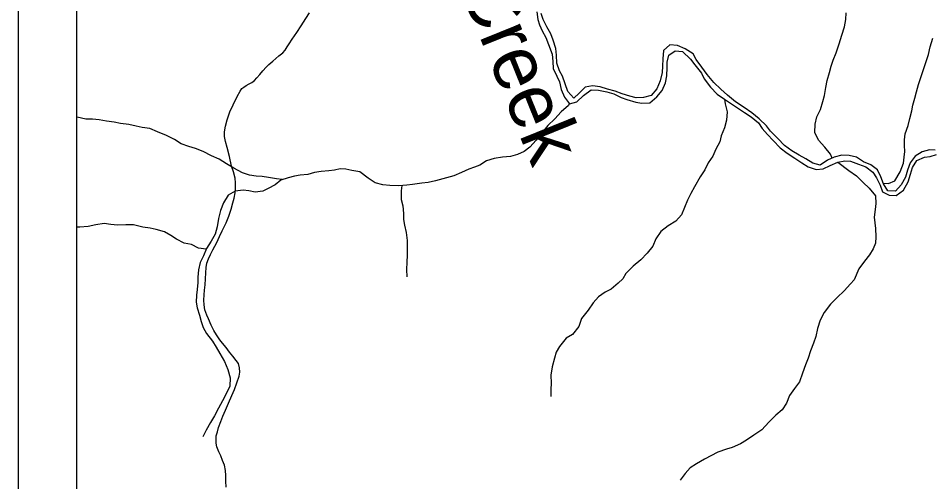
# Model space of a CAD drawing. Extents: x 0 to 44, y -23.8 to 22.
# Drawn here: x 2 to 3.565, y 16.572 to 17.366 of the extents above; entities that cross this region are included whole.
import ezdxf

# ---------------------------------------------------------------- set-up
doc = ezdxf.new("R2010")
doc.units = 0
for name, color, linetype in [('Default', 7, 'Continuous'), ('GM_X_Minor_River', 7, 'Continuous'), ('GM_X_Minor_River_Text', 7, 'Continuous'), ('GM_X_Township_Road', 7, 'Continuous'), ('SH_Cut_Line', 7, 'Continuous'), ('SH_Data', 7, 'Continuous')]:
    doc.layers.add(name, color=color, linetype=linetype)

msp = doc.modelspace()

# ---------------------------------------------------------------- linework, layer by layer
at = {"layer": 'Default'}
msp.add_lwpolyline([(2.3497, 20.9), (2.1, 20.9), (2.1, 14.1), (2.838, 14.1), (3.0317, 14.1856), (3.8639, 14.5533), (4.3443, 14.7655), (4.4538, 14.8144), (4.856, 14.9939), (4.5387, 15.7097), (4.3476, 16.1408), (4.1422, 16.6361), (4.026, 16.9163), (3.7907, 17.4383), (3.763, 17.5087), (3.455, 18.29), (3.1789, 18.9421), (3.1321, 19.0527), (3.0496, 19.2474), (3.0092, 19.3427), (2.8013, 19.8369), (2.472, 20.6113)], close=True, dxfattribs=at)
at = {"layer": 'GM_X_Minor_River'}
for points in [[(2.888, 17.377), (2.8901, 17.3638), (2.8931, 17.3543), (2.8975, 17.3444), (2.9039, 17.3326), (2.908, 17.3208), (2.9143, 17.3044), (2.9157, 17.2919), (2.9163, 17.2798), (2.9223, 17.2668), (2.9271, 17.2569), (2.9297, 17.244), (2.9356, 17.2307), (2.9442, 17.2189), (2.9568, 17.2226), (2.9682, 17.2335), (2.9815, 17.2432), (2.9936, 17.2428), (3.0084, 17.24), (3.0201, 17.2361), (3.0325, 17.2303), (3.0423, 17.2268), (3.0578, 17.2218), (3.068, 17.2202), (3.082, 17.2208), (3.0939, 17.231), (3.1027, 17.2423), (3.1088, 17.2551), (3.1112, 17.2672), (3.1117, 17.2813), (3.1117, 17.2907), (3.1141, 17.3025), (3.1251, 17.31), (3.138, 17.3091), (3.1515, 17.2957), (3.159, 17.2858), (3.1703, 17.2717), (3.1751, 17.2618), (3.1856, 17.2477), (3.1972, 17.2355), (3.2096, 17.227)], [(3.2692, 17.1936), (3.2564, 17.2035), (3.2432, 17.2131), (3.2285, 17.2227), (3.2146, 17.2342), (3.2037, 17.2441), (3.1917, 17.256), (3.1801, 17.2693), (3.1711, 17.2819), (3.161, 17.2949), (3.1561, 17.3048), (3.1422, 17.3132), (3.129, 17.319), (3.1161, 17.3203), (3.1051, 17.3105), (3.1038, 17.2965), (3.1037, 17.2836), (3.1029, 17.2726), (3.0998, 17.2586), (3.094, 17.2446), (3.084, 17.2333), (3.0711, 17.23), (3.0586, 17.2294), (3.0473, 17.2325), (3.0345, 17.2364), (3.0224, 17.2406), (3.0092, 17.2441), (2.9967, 17.2484), (2.9835, 17.25), (2.9713, 17.2479), (2.961, 17.2377), (2.9515, 17.2291), (2.9414, 17.2401), (2.9366, 17.2534), (2.9321, 17.2664), (2.9269, 17.2759), (2.9225, 17.2888), (2.9218, 17.3028), (2.9208, 17.3138), (2.9163, 17.3283), (2.9123, 17.3393), (2.9052, 17.3511), (2.8992, 17.3637), (2.8959, 17.374)], [(3.3941, 17.1264), (3.391, 17.1327), (3.3816, 17.1449), (3.3707, 17.1571), (3.3644, 17.1701), (3.3653, 17.1841), (3.3676, 17.197), (3.3742, 17.2094), (3.3781, 17.2234), (3.3808, 17.2336), (3.3835, 17.2469), (3.3855, 17.259), (3.3894, 17.2726), (3.3922, 17.2836), (3.396, 17.2942), (3.401, 17.3067), (3.4061, 17.3222), (3.4108, 17.3369), (3.415, 17.3513), (3.4178, 17.3638), (3.4182, 17.3748)], [(3.4815, 17.0831), (3.4909, 17.083), (3.5015, 17.0875), (3.5107, 17.1026), (3.5161, 17.1177), (3.5177, 17.1279), (3.5186, 17.1378), (3.5183, 17.148), (3.518, 17.1575), (3.5192, 17.1677), (3.5242, 17.1821), (3.5273, 17.1942), (3.5305, 17.2071), (3.5324, 17.2169), (3.5356, 17.229), (3.5387, 17.2396), (3.5422, 17.2521), (3.5453, 17.2627), (3.5507, 17.2778), (3.555, 17.2918), (3.5592, 17.3035), (3.562, 17.3171), (3.5663, 17.3319)], [(2.9437, 17.2196), (2.9423, 17.2162), (2.9301, 17.2057), (2.9191, 17.1937), (2.9072, 17.182), (2.8962, 17.1684), (2.887, 17.1571), (2.8763, 17.1451), (2.8668, 17.1376), (2.8554, 17.1324), (2.8429, 17.1291), (2.8296, 17.1276), (2.8152, 17.1255), (2.8023, 17.1214), (2.7909, 17.1143), (2.7814, 17.1106), (2.7719, 17.1072), (2.759, 17.1017), (2.7461, 17.0957), (2.7271, 17.0905), (2.7146, 17.0872), (2.7021, 17.0847), (2.6911, 17.0832), (2.6752, 17.0811), (2.6653, 17.08), (2.6517, 17.079), (2.6362, 17.0791), (2.6244, 17.0803), (2.6116, 17.0839), (2.5996, 17.0919), (2.5853, 17.1026), (2.5716, 17.105), (2.5611, 17.1074), (2.5512, 17.1078), (2.5414, 17.1053), (2.5319, 17.1042), (2.519, 17.1032), (2.5073, 17.1014), (2.4959, 17.0984), (2.483, 17.097), (2.4732, 17.0952), (2.4625, 17.0926), (2.4496, 17.0885), (2.4401, 17.0807), (2.4283, 17.0739), (2.4188, 17.0698), (2.4059, 17.068), (2.395, 17.07), (2.3852, 17.0712), (2.3715, 17.0698), (2.3597, 17.0627), (2.3517, 17.0495), (2.3463, 17.0363), (2.3431, 17.023), (2.3407, 17.0086), (2.3372, 16.9958), (2.3303, 16.9837), (2.3227, 16.9716), (2.3173, 16.9591), (2.3115, 16.9474), (2.3088, 16.9349), (2.3073, 16.9221)], [(3.2096, 17.227), (3.2107, 17.2194), (3.214, 17.2054), (3.2132, 17.1914), (3.2096, 17.1781), (3.2042, 17.1645), (3.2015, 17.1539), (3.1946, 17.1418), (3.19, 17.1297), (3.1815, 17.1181), (3.1758, 17.1063), (3.1681, 17.0943), (3.1585, 17.0773), (3.152, 17.0656), (3.1466, 17.0542), (3.1412, 17.0418), (3.1362, 17.0293), (3.1266, 17.0184), (3.1133, 17.0105), (3.1004, 17.0004), (3.0919, 16.9879), (3.0869, 16.9755), (3.0774, 16.9634), (3.0663, 16.9521), (3.053, 16.9409), (3.0408, 16.9288), (3.0354, 16.9194)], [(3.2096, 17.227), (3.2217, 17.219), (3.2319, 17.2121), (3.2439, 17.2044), (3.2552, 17.1967), (3.268, 17.1868), (3.2744, 17.1772), (3.2834, 17.1669), (3.2931, 17.1566), (3.3048, 17.144), (3.3172, 17.1344), (3.33, 17.126), (3.342, 17.1179), (3.3533, 17.1114), (3.3665, 17.1067), (3.379, 17.1078), (3.3908, 17.1138), (3.4037, 17.119), (3.4159, 17.1215), (3.4257, 17.1211), (3.4393, 17.116), (3.4517, 17.111), (3.4638, 17.1022), (3.4698, 17.0927), (3.4765, 17.0801), (3.4805, 17.0683), (3.4919, 17.0625), (3.504, 17.0621), (3.5165, 17.0714), (3.5246, 17.0858), (3.5281, 17.0986), (3.5316, 17.1104), (3.5389, 17.1224), (3.5522, 17.128), (3.562, 17.1291), (3.5727, 17.1324)], [(2.4519, 17.0893), (2.4425, 17.0905), (2.4289, 17.0929), (2.4175, 17.0945), (2.4077, 17.0953), (2.396, 17.0969), (2.3839, 17.1008), (2.3695, 17.1089), (2.3567, 17.1162), (2.3443, 17.1242), (2.3311, 17.1304), (2.3168, 17.1374), (2.3036, 17.1428), (2.2922, 17.1463), (2.279, 17.1509), (2.2674, 17.1582), (2.2538, 17.1651), (2.2387, 17.1713), (2.2255, 17.1771), (2.2123, 17.1787), (2.2021, 17.1807), (2.1896, 17.1839), (2.1752, 17.1855), (2.1643, 17.1875), (2.1514, 17.1895), (2.1386, 17.1918), (2.1272, 17.1931), (2.1155, 17.1932), (2.1007, 17.1963), (2.1, 17.1965)], [(3.5708, 17.14), (3.5606, 17.1405), (3.5481, 17.1372), (3.5363, 17.1297), (3.5275, 17.1184), (3.5232, 17.1055), (3.5197, 17.0934), (3.5124, 17.0802), (3.5025, 17.0696), (3.4893, 17.0701), (3.4818, 17.0823), (3.4777, 17.0941), (3.4718, 17.1063), (3.4605, 17.1147), (3.448, 17.1201), (3.4356, 17.1278), (3.4231, 17.1309), (3.4106, 17.131), (3.3977, 17.1281), (3.386, 17.1225), (3.3734, 17.1139), (3.3613, 17.1178), (3.3489, 17.1247), (3.3376, 17.1312), (3.3252, 17.1389), (3.3127, 17.1481), (3.3011, 17.1596), (3.2883, 17.1722), (3.2816, 17.1817), (3.2692, 17.1936)], [(3.4037, 17.119), (3.4229, 17.1052), (3.4357, 17.0956), (3.4474, 17.0845), (3.4575, 17.0749), (3.4684, 17.0616), (3.469, 17.0483), (3.4678, 17.0381), (3.4658, 17.0248), (3.4673, 17.0153), (3.4683, 17.0058), (3.469, 16.9914), (3.4685, 16.9808), (3.4646, 16.971), (3.4581, 16.9608), (3.4497, 16.9499), (3.4398, 16.9363), (3.4321, 16.918)], [(2.6569, 17.0794), (2.6558, 17.0702), (2.656, 17.0551), (2.6586, 17.0444), (2.66, 17.0315), (2.6599, 17.0213), (2.6618, 17.0114), (2.6643, 16.9989), (2.6661, 16.9852), (2.6664, 16.972), (2.6659, 16.9602), (2.6654, 16.9481), (2.6649, 16.9356), (2.6656, 16.9227)], [(2.322, 16.9701), (2.309, 16.9721), (2.297, 16.9783), (2.2841, 16.9806), (2.2713, 16.9876), (2.2611, 16.9937), (2.2506, 16.9999), (2.2362, 17.0041), (2.2257, 17.0065), (2.2136, 17.0077), (2.1973, 17.012), (2.1841, 17.0118), (2.1697, 17.0115), (2.1587, 17.0127), (2.147, 17.0143), (2.1326, 17.0122), (2.1197, 17.0088), (2.1057, 17.0082), (2.1, 17.0081)], [(2.3073, 16.9221), (2.3078, 16.9133), (2.3062, 16.9012), (2.3054, 16.8913), (2.3049, 16.8792), (2.3064, 16.8697), (2.3105, 16.8571), (2.3134, 16.8465), (2.3168, 16.8362), (2.3224, 16.8256), (2.3329, 16.8126), (2.3389, 16.8024), (2.3452, 16.7913), (2.3535, 16.7776), (2.3587, 16.7643), (2.3631, 16.7499), (2.3623, 16.7355), (2.3573, 16.7245), (2.35, 16.7105), (2.3428, 16.698), (2.3363, 16.6848), (2.3294, 16.6731), (2.3221, 16.6602), (2.316, 16.6489)], [(3.0354, 16.9194), (3.0278, 16.912), (3.0153, 16.9018), (3.0054, 16.8966), (2.994, 16.8887), (2.9845, 16.8781), (2.9761, 16.866), (2.965, 16.8513), (2.9604, 16.8377), (2.9494, 16.8241), (2.9384, 16.8177), (2.9269, 16.8037), (2.9216, 16.7939), (2.9185, 16.7833), (2.9146, 16.7685), (2.9122, 16.7545), (2.9129, 16.7409), (2.9121, 16.7299), (2.912, 16.7181)], [(3.4321, 16.918), (3.4256, 16.9107), (3.4149, 16.8986), (3.4028, 16.8877), (3.391, 16.876), (3.3807, 16.862), (3.3738, 16.8488), (3.3692, 16.8341), (3.3664, 16.8208), (3.3622, 16.8094), (3.3572, 16.7962), (3.353, 16.7833), (3.3487, 16.772), (3.3434, 16.758), (3.338, 16.7432), (3.3296, 16.7315), (3.3208, 16.7194), (3.3158, 16.7066), (3.3086, 16.6952), (3.2979, 16.6858), (3.2857, 16.6737), (3.2736, 16.6609), (3.2599, 16.6515), (3.2474, 16.6432), (3.2371, 16.6369), (3.2227, 16.6305), (3.2132, 16.6275), (3.1985, 16.6227), (3.1757, 16.6107), (3.1617, 16.6028), (3.151, 16.5957), (3.1426, 16.5859), (3.1335, 16.5745)]]:
    msp.add_lwpolyline(points, dxfattribs=at)
at = {"layer": 'GM_X_Township_Road'}
msp.add_lwpolyline([(2.356, 16.5626), (2.3558, 16.5728), (2.3554, 16.5825), (2.3549, 16.5913), (2.3533, 16.6004), (2.3501, 16.6083), (2.347, 16.6161), (2.3438, 16.6231), (2.3402, 16.6317), (2.339, 16.6382), (2.3387, 16.6448), (2.339, 16.6505), (2.3411, 16.6574), (2.3432, 16.665), (2.3469, 16.6749), (2.3505, 16.6844), (2.355, 16.6947), (2.3602, 16.7067), (2.3657, 16.7198), (2.3705, 16.7299), (2.3745, 16.7412), (2.3783, 16.7528), (2.3794, 16.7598), (2.3792, 16.7671), (2.3775, 16.7745), (2.3733, 16.7796), (2.3676, 16.7871), (2.3619, 16.7941), (2.356, 16.8017), (2.3499, 16.809), (2.3453, 16.8151), (2.3394, 16.8238), (2.3349, 16.8309), (2.3305, 16.8398), (2.3257, 16.8507), (2.3231, 16.8573), (2.3198, 16.8663), (2.3183, 16.875), (2.3179, 16.8829), (2.3183, 16.8918), (2.3189, 16.9002), (2.32, 16.9089), (2.3206, 16.9196), (2.3213, 16.9295), (2.3221, 16.9386), (2.3232, 16.9465), (2.3259, 16.9537), (2.3295, 16.9613), (2.3333, 16.9689), (2.3402, 16.9819), (2.3448, 16.9918), (2.3495, 17.0017), (2.356, 17.0152), (2.3608, 17.0268), (2.3646, 17.039), (2.3678, 17.0497), (2.3697, 17.0575), (2.3714, 17.0666), (2.372, 17.074), (2.3722, 17.0836), (2.3714, 17.0921), (2.3686, 17.1028), (2.3653, 17.1123), (2.3617, 17.1289), (2.3581, 17.1445), (2.3552, 17.1544), (2.3535, 17.1635), (2.3531, 17.1715), (2.355, 17.1807), (2.3581, 17.1919), (2.3623, 17.2053), (2.368, 17.2174), (2.375, 17.2315), (2.38, 17.2411), (2.3832, 17.2452), (2.3861, 17.2477), (2.3901, 17.2508), (2.3954, 17.2534), (2.3998, 17.2557), (2.4044, 17.2591), (2.4086, 17.2639), (2.4139, 17.2696), (2.419, 17.2755), (2.4246, 17.2818), (2.4293, 17.2864), (2.4358, 17.2925), (2.4409, 17.2967), (2.4465, 17.3012), (2.4529, 17.3064), (2.4569, 17.3111), (2.4605, 17.317), (2.4638, 17.322), (2.4691, 17.3302), (2.4769, 17.3416), (2.4845, 17.353), (2.4927, 17.3652), (2.4986, 17.3753)], dxfattribs=at)
at = {"layer": 'SH_Cut_Line'}
msp.add_lwpolyline([(4.3476, 16.1408), (4.1422, 16.6361), (4.026, 16.9163), (3.7907, 17.4383), (3.763, 17.5087), (3.455, 18.29), (3.5135, 19.1552), (3.5139, 19.1608), (3.5639, 19.9016), (3.5995, 20.4294), (3.5996, 20.4304), (3.6002, 20.4391), (3.6191, 20.7184), (3.9141, 20.6975), (4.3639, 20.6657), (6.7023, 20.5094), (6.7107, 20.5383), (6.8158, 20.9), (2.1, 20.9), (2.1, 14.1)], dxfattribs=at)
at = {"layer": 'SH_Data'}
for p, q in [((2, 21), (2, 14)), ((2.1, 20.9), (2.1, 14.1))]:
    msp.add_line(p, q, dxfattribs=at)

# ---------------------------------------------------------------- texts
at = {"layer": 'GM_X_Minor_River_Text'}
msp.add_text('Creek', height=0.09469, rotation=292.0026, dxfattribs=at).set_placement((2.7544, 17.4219))

doc.saveas('drawing.dxf')
